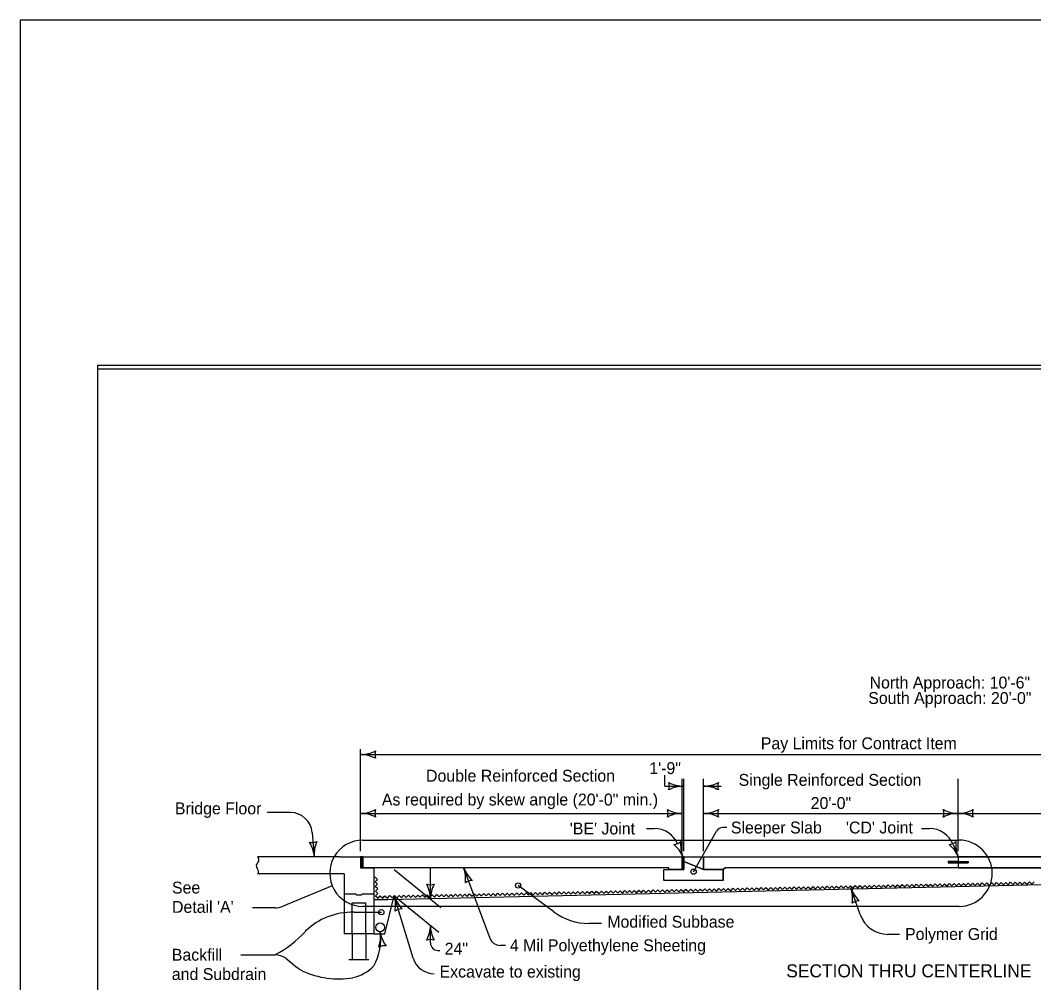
# Model space of a CAD drawing. Extents: x 10028 to 81668, y 6395 to 11634.
# Drawn here: x 20828 to 22193, y 9112 to 10409 of the extents above; entities that cross this region are included whole.
import ezdxf

# ---------------------------------------------------------------- set-up
doc = ezdxf.new("R2010")
doc.units = 0
for name, color, linetype in [('Default', 7, 'Continuous'), ('dsnCellElements', 7, 'Continuous'), ('dsnstdblockInterim', 7, 'Continuous'), ('dsnStdBlockNotModified', 7, 'Continuous'), ('dsnStdDimension', 7, 'Continuous'), ('dsnStgShadingPropPav', 7, 'Continuous'), ('ShtPlotIdentification', 7, 'Continuous')]:
    doc.layers.add(name, color=color, linetype=linetype)

msp = doc.modelspace()

# ---------------------------------------------------------------- linework, layer by layer
at = {"layer": 'Default'}
msp.add_lwpolyline([(20932.5, 9944), (24067.5, 9944), (24067.5, 7924), (20932.5, 7924)], close=True, dxfattribs=at)
at = {"layer": 'dsnCellElements'}
for p, q in [((21286.5, 9289.1), (21286.5, 9426.7)), ((21286.5, 9419.3), (22626, 9419.3)), ((21696.4, 9376.7), (21696.4, 9391.4)), ((21719.7, 9289.1), (21719.7, 9386.8)), ((21721.6, 9289.1), (21721.6, 9386.8)), ((21748.3, 9289.1), (21748.3, 9386.8)), ((22091.4, 9289.1), (22091.4, 9386.8)), ((21696.4, 9376.7), (21721.6, 9376.7)), ((21748.3, 9376.7), (21772.3, 9376.7)), ((21286.5, 9340.1), (21719.7, 9340.1)), ((21748.3, 9340.1), (22091.4, 9340.1)), ((22091.4, 9340.1), (22447.8, 9340.1)), ((21221.3, 9314.2), (21224.1, 9281.7)), ((21671.4, 9319.7), (21681.7, 9319.7)), ((21735, 9261.5), (21765.7, 9315.9)), ((21779.8, 9321), (21774.4, 9321)), ((22042.1, 9319.7), (22052.4, 9319.7)), ((21289.5, 9304), (22092.6, 9304)), ((21289.5, 9266.8), (21289.5, 9281.7)), ((21289.5, 9281.7), (21719.7, 9281.7)), ((21719.7, 9281.7), (21719.7, 9275.2)), ((21719.7, 9275.2), (21719.7, 9275.2)), ((21719.7, 9275.2), (21719.7, 9264.5)), ((21748.3, 9264.5), (21721.6, 9275.2)), ((21721.6, 9275.2), (21748.3, 9264.5)), ((21748.3, 9264.5), (21748.3, 9281.7)), ((21748.3, 9281.7), (22091.4, 9281.7)), ((22091.4, 9275.2), (22078, 9275.2)), ((22078, 9275.2), (22078, 9273.3)), ((22078, 9273.3), (22091.4, 9273.3)), ((22091.4, 9281.7), (22091.4, 9275.2)), ((22091.4, 9273.3), (22091.4, 9266.8)), ((21304.3, 9266.8), (21289.5, 9266.8)), ((21326.6, 9266.8), (21304.3, 9266.8)), ((21701.5, 9266.8), (21326.6, 9266.8)), ((21331.7, 9264.4), (21394.5, 9213.3)), ((21380.5, 9224.7), (21380.5, 9265.9)), ((21425.2, 9266.8), (21460.5, 9172.1)), ((21701.5, 9264.5), (21701.5, 9266.8)), ((21719.7, 9264.5), (21701.5, 9264.5)), ((21775, 9264.5), (21748.3, 9264.5)), ((21777.5, 9266.8), (21775, 9264.5)), ((21775, 9264.5), (21775, 9264.5)), ((22091.4, 9266.8), (21777.5, 9266.8)), ((21248.3, 9242.4), (21182.1, 9215.1)), ((21546.7, 9207.3), (21498.7, 9242.9)), ((21331.7, 9229.1), (21392, 9180)), ((21357.3, 9145.2), (21331.7, 9229.1)), ((21959.4, 9203.7), (21946.9, 9239.7)), ((21289.5, 9214.9), (22092.6, 9214.9)), ((21170.8, 9212.8), (21140.7, 9212.8)), ((21277.6, 9206.9), (21314.4, 9206.9)), ((21380.5, 9165.5), (21380.5, 9189.4)), ((21610.8, 9191.7), (21593.9, 9191.7)), ((22012.1, 9177.1), (21996.8, 9177.1)), ((21481.5, 9162.3), (21474.6, 9162.3)), ((21125.1, 9149.5), (21170.8, 9149.5)), ((21390.5, 9155.5), (21393, 9155.5))]:
    msp.add_line(p, q, dxfattribs=at)
for centre, radius, start, end in [((21681.8, 9285), 34.7, 22.5907, 90), ((21774.4, 9311), 10, 90, 150.5496), ((22052.4, 9285), 34.7, 22.5907, 90), ((21289.5, 9259.4), 44.6, 89.9996, 270), ((22092.6, 9259.4), 44.6, 270.0011, 90), ((21170.8, 9242.5), 29.7, 270, 292.4496), ((21275.4, 9116.1), 90.9, 88.6098, 134.2601), ((21593.9, 9270.9), 79.2, 233.4243, 270), ((21996.8, 9216.7), 39.6, 199.1769, 270), ((21107.3, 9274.8), 140.5, 296.876, 318.179), ((21242.3, 9169.9), 71.3, 330.5092, 8.5915), ((21474.6, 9177.3), 15, 200.4159, 270), ((21297.2, 9265), 163.6, 227.1442, 236.9942), ((21264.3, 9172.5), 55, 282.277, 316.7198), ((21385.7, 9153.8), 29.7, 196.9535, 270), ((21257.1, 9235.6), 118.5, 245.5915, 279.2221)]:
    msp.add_arc(centre, radius, start, end, dxfattribs=at)
at = {"layer": 'dsnstdblockInterim'}
msp.add_lwpolyline([(20932.5, 9939), (24067.5, 9939), (24067.5, 7929), (20932.5, 7929)], close=True, dxfattribs=at)
at = {"layer": 'dsnStdBlockNotModified'}
for centre, radius, start, end in [((21286.5, 9461.8), 42.5, 270, 298.0725), ((21286.5, 9376.8), 42.5, 61.9275, 90), ((21322.1, 9419.3), 16.4, 162.2666, 197.7334), ((21686, 9376.7), 16.4, 342.2666, 17.7333), ((21721.6, 9419.2), 42.5, 241.9275, 270), ((21748.3, 9419.2), 42.5, 270, 298.0725), ((21784, 9376.7), 16.4, 162.2666, 197.7334), ((21721.6, 9334.2), 42.5, 90, 118.0725), ((21748.3, 9334.2), 42.5, 61.9275, 90), ((21286.5, 9382.6), 42.5, 270, 298.0725), ((21286.5, 9297.6), 42.5, 61.9275, 90), ((21322.1, 9340.1), 16.4, 162.2666, 197.7334), ((21684.1, 9340.1), 16.4, 342.2666, 17.7333), ((21719.7, 9382.6), 42.5, 241.9275, 270), ((21719.7, 9297.6), 42.5, 90, 118.0725), ((21748.3, 9382.6), 42.5, 270, 298.0725), ((21748.3, 9297.6), 42.5, 61.9275, 90), ((21784, 9340.1), 16.4, 162.2666, 197.7334), ((22055.7, 9340.1), 16.4, 342.2666, 17.7333), ((22091.4, 9382.6), 42.5, 241.9275, 270), ((22091.4, 9297.6), 42.5, 90, 118.0725), ((22091.4, 9382.6), 42.5, 270, 298.0725), ((22091.4, 9297.6), 42.5, 61.9275, 90), ((22127, 9340.1), 16.4, 162.2666, 197.7334), ((21221.1, 9317.2), 16.4, 257.2333, 292.7), ((21181.8, 9278), 42.5, 4.9667, 33.0392), ((21266.5, 9285.4), 42.5, 156.8942, 184.9667), ((21707, 9314.6), 16.4, 274.8653, 310.332), ((21681.4, 9265.4), 42.5, 22.5986, 50.6711), ((21759.9, 9298), 42.5, 174.5261, 202.5986), ((22077.7, 9314.6), 16.4, 274.8653, 310.332), ((22052.1, 9265.4), 42.5, 22.5986, 50.6711), ((22130.6, 9298), 42.5, 174.5261, 202.5986), ((21465.1, 9281.6), 42.5, 200.3742, 228.4467), ((21385.4, 9252), 42.5, 352.3017, 20.3742), ((21437.7, 9233.4), 16.4, 92.6409, 128.1076), ((21372.4, 9241.5), 42.5, 196.9516, 225.0241), ((21291.1, 9216.7), 42.5, 348.8791, 16.9516), ((21987, 9253.6), 42.5, 199.1744, 227.2469), ((21906.7, 9225.7), 42.5, 351.1019, 19.1744), ((21958.6, 9206), 16.4, 91.4411, 126.9078), ((21342.1, 9195), 16.4, 89.2182, 124.6849), ((21338, 9189.4), 42.5, 331.9275, 360), ((21423, 9189.4), 42.5, 180, 208.0725), ((21270.8, 9174.2), 42.5, 340.519, 8.5915), ((21354.8, 9186.9), 42.5, 188.5915, 216.6639), ((21318.1, 9145.3), 16.4, 80.8581, 116.3248), ((21380.5, 9153.7), 16.4, 72.2666, 107.7334)]:
    msp.add_arc(centre, radius, start, end, dxfattribs=at)
at = {"layer": 'dsnStdDimension'}
msp.add_lwpolyline([(20828, 7824.5), (24172, 7824.5), (24172, 10408.5), (20828, 10408.5)], close=True, dxfattribs=at)
at = {"layer": 'dsnStgShadingPropPav'}
for centre in [(21735, 9261.5), (21498.7, 9242.9), (21314.4, 9206.9)]:
    msp.add_circle(centre, 3.54, dxfattribs=at)
at = {"layer": 'ShtPlotIdentification'}
for p, q in [((21192.2, 9341.3), (21160.5, 9341.3)), ((22084.4, 9298.3), (22091.4, 9281.7)), ((21258.3, 9281.7), (21147.7, 9281.7)), ((21258.3, 9281.7), (21286.5, 9281.7)), ((21286.5, 9281.7), (21286.5, 9266.7)), ((21289.5, 9281.7), (21286.5, 9281.7)), ((21286.5, 9280.4), (21287.4, 9281.3)), ((21286.5, 9278.3), (21289.5, 9281.3)), ((21289.5, 9281.3), (21286.5, 9281.3)), ((21286.5, 9276.2), (21289.5, 9279.2)), ((21286.5, 9274.1), (21289.5, 9277.1)), ((21286.5, 9272), (21289.5, 9275)), ((21286.5, 9269.9), (21289.5, 9272.9)), ((21286.5, 9267.8), (21289.5, 9270.8)), ((21289.5, 9281.7), (21289.5, 9266.7)), ((21289.5, 9281.7), (21719.7, 9281.7)), ((21719.7, 9264.5), (21719.7, 9281.7)), ((21721.6, 9281.7), (21719.7, 9281.7)), ((21719.7, 9281.7), (21721.6, 9281.7)), ((21719.7, 9264.5), (21719.7, 9281.7)), ((21721.6, 9281.7), (21748.3, 9281.7)), ((21721.6, 9281.7), (21721.6, 9264.5)), ((21721.6, 9281.7), (21721.6, 9264.5)), ((21721.6, 9281.7), (21748.3, 9281.7)), ((21721.6, 9264.5), (21721.6, 9281.7)), ((21748.3, 9264.5), (21748.3, 9281.7)), ((21748.3, 9281.7), (22444.4, 9281.7)), ((21748.3, 9281.7), (21748.3, 9264.5)), ((22078, 9275.2), (22104.7, 9275.2)), ((22078, 9275.2), (22078, 9273.3)), ((22078, 9273.3), (22104.7, 9273.3)), ((22444.4, 9281.7), (22091.4, 9281.7)), ((22091.4, 9281.7), (22091.4, 9275.2)), ((22091.4, 9281.7), (22091.4, 9266.8)), ((22091.4, 9275.2), (22104.7, 9275.2)), ((22104.7, 9273.3), (22091.4, 9273.3)), ((22091.4, 9273.3), (22091.4, 9266.8)), ((22104.7, 9275.2), (22104.7, 9273.3)), ((22104.7, 9275.2), (22104.7, 9273.3)), ((21264.2, 9258.8), (21147.7, 9258.8)), ((21264.2, 9258.8), (21264.2, 9178)), ((21286.5, 9266.7), (21304.3, 9266.7)), ((21287.5, 9266.7), (21289.5, 9268.7)), ((21701.5, 9266.8), (21289.5, 9266.8)), ((21326.6, 9266.8), (21303.3, 9266.8)), ((21304.3, 9266.8), (21304.3, 9178)), ((21694.9, 9249.6), (21694.9, 9264.5)), ((21694.9, 9264.5), (21701.5, 9264.5)), ((21694.9, 9249.6), (21694.9, 9264.5)), ((21694.9, 9264.5), (21701.5, 9264.5)), ((21701.5, 9264.5), (21701.5, 9266.8)), ((21701.5, 9264.5), (21721.6, 9264.5)), ((21701.5, 9264.5), (21721.6, 9264.5)), ((21721.6, 9264.5), (21719.7, 9264.5)), ((21775, 9264.5), (21748.3, 9264.5)), ((21748.3, 9264.5), (21775, 9264.5)), ((21775, 9264.5), (21777.5, 9266.8)), ((21775, 9249.6), (21775, 9264.5)), ((21775, 9264.5), (21775, 9249.6)), ((22430.7, 9266.8), (21777.5, 9266.8)), ((22091.4, 9266.8), (22430.7, 9266.8)), ((22440.3, 9249), (21323.1, 9223.8)), ((21775, 9249.6), (21694.9, 9249.6)), ((21775, 9249.6), (21694.9, 9249.6)), ((21264.2, 9231.7), (21279.3, 9231.7)), ((21281.2, 9229.9), (21279.3, 9231.7)), ((21287.3, 9229.9), (21281.2, 9229.9)), ((21287.3, 9229.9), (21289.2, 9231.7)), ((21289.2, 9231.7), (21304.3, 9231.7)), ((21319.2, 9178), (21331.7, 9229.1)), ((21275, 9178), (21275, 9219.6)), ((21275, 9219.6), (21293.5, 9219.6)), ((21293.5, 9178), (21293.5, 9219.6)), ((21323.1, 9223.8), (21304.3, 9223.8)), ((21304.3, 9178), (21264.2, 9178)), ((21275, 9178), (21275, 9143.1)), ((21293.5, 9178), (21293.5, 9143.1)), ((21304.3, 9178), (21319.2, 9178)), ((21270.7, 9143.1), (21297.7, 9143.1))]:
    msp.add_line(p, q, dxfattribs=at)
for points in [[(22091.4, 9281.7), (22091.4, 9281.7)], [(21308.3, 9227.3), (21306.5, 9229), (21309.6, 9232.2), (21306.4, 9235.3), (21309.5, 9238.6), (21306.2, 9241.7), (21309.3, 9244.9), (21306.1, 9248), (21309.2, 9251.2), (21305.9, 9254.3), (21306.1, 9254.5)], [(21897.4, 9239.9), (21899, 9238.4), (21902.1, 9241.6), (21905.3, 9238.5), (21908.4, 9241.7), (21911.7, 9238.6), (21914.8, 9241.9), (21918, 9238.8), (21921.1, 9242), (21924.3, 9238.9), (21927.4, 9242.2), (21930.7, 9239.1), (21933.8, 9242.3), (21937, 9239.2), (21940.1, 9242.4), (21943.3, 9239.3), (21946.4, 9242.6), (21949.7, 9239.5), (21952.8, 9242.7), (21956, 9239.6), (21959.1, 9242.8), (21962.3, 9239.7), (21965.4, 9243), (21968.7, 9239.9), (21971.8, 9243.1), (21973.4, 9241.6)], [(21973.4, 9241.6), (21975, 9240), (21978.1, 9243.2), (21981.3, 9240.1), (21984.4, 9243.4), (21987.7, 9240.3), (21990.8, 9243.5), (21994, 9240.4), (21997.1, 9243.6), (22000.3, 9240.5), (22003.5, 9243.8), (22006.7, 9240.7), (22009.8, 9243.9), (22013, 9240.8), (22016.1, 9244.1), (22019.4, 9241), (22022.5, 9244.2), (22025.7, 9241.1), (22028.8, 9244.3), (22032, 9241.2), (22035.1, 9244.5), (22038.4, 9241.4), (22041.5, 9244.6), (22044.7, 9241.5), (22047.8, 9244.7), (22049.4, 9243.2)], [(22049.4, 9243.2), (22051, 9241.6), (22054.1, 9244.9), (22057.4, 9241.8), (22060.5, 9245), (22063.7, 9241.9), (22066.8, 9245.1), (22070, 9242), (22073.1, 9245.3), (22076.4, 9242.2), (22079.5, 9245.4), (22082.7, 9242.3), (22085.8, 9245.5), (22089, 9242.4), (22092.1, 9245.7), (22095.4, 9242.6), (22098.5, 9245.8), (22101.7, 9242.7), (22104.8, 9246), (22108, 9242.9), (22111.1, 9246.1), (22114.4, 9243), (22117.5, 9246.2), (22120.7, 9243.1), (22123.8, 9246.4), (22125.4, 9244.8)], [(22125.4, 9244.8), (22127, 9243.3), (22130.1, 9246.5), (22133.4, 9243.4), (22136.5, 9246.6), (22139.7, 9243.5), (22142.8, 9246.8), (22146, 9243.7), (22149.1, 9246.9), (22152.4, 9243.8), (22155.5, 9247), (22158.7, 9243.9), (22161.8, 9247.2), (22165, 9244.1), (22168.1, 9247.3), (22171.4, 9244.2), (22174.5, 9247.4), (22177.7, 9244.3), (22180.8, 9247.6), (22184.1, 9244.5), (22187.2, 9247.7), (22190.4, 9244.6), (22193.5, 9247.8)], [(21306.6, 9228.9), (21306.6, 9228.9), (21309.9, 9225.8), (21313, 9229), (21316.2, 9225.9), (21319.3, 9229.1), (21322.6, 9226), (21325.7, 9229.3), (21328.9, 9226.2), (21332, 9229.4), (21335.2, 9226.3), (21338.3, 9229.6), (21341.6, 9226.5), (21344.7, 9229.7), (21347.9, 9226.6), (21351, 9229.8), (21354.2, 9226.7), (21357.3, 9230), (21360.6, 9226.9), (21363.7, 9230.1), (21365.3, 9228.5)], [(21365.3, 9228.5), (21366.9, 9227), (21370, 9230.2), (21373.2, 9227.1), (21376.3, 9230.4), (21379.6, 9227.3), (21382.7, 9230.5), (21385.9, 9227.4), (21389, 9230.6), (21392.2, 9227.5), (21395.3, 9230.8), (21398.6, 9227.7), (21401.7, 9230.9), (21404.9, 9227.8), (21408, 9231), (21411.2, 9227.9), (21414.3, 9231.2), (21417.6, 9228.1), (21420.7, 9231.3), (21423.9, 9228.2), (21427, 9231.4), (21430.2, 9228.3), (21433.3, 9231.6), (21436.6, 9228.5), (21439.7, 9231.7), (21441.3, 9230.2)], [(21441.3, 9230.2), (21442.9, 9228.6), (21446, 9231.9), (21449.2, 9228.8), (21452.3, 9232), (21455.6, 9228.9), (21458.7, 9232.1), (21461.9, 9229), (21465, 9232.3), (21468.2, 9229.2), (21471.3, 9232.4), (21474.6, 9229.3), (21477.7, 9232.5), (21480.9, 9229.4), (21484, 9232.7), (21487.2, 9229.6), (21490.3, 9232.8), (21493.6, 9229.7), (21496.7, 9232.9), (21499.9, 9229.8), (21503, 9233.1), (21506.3, 9230), (21509.4, 9233.2), (21512.6, 9230.1), (21515.7, 9233.4), (21517.3, 9231.8)], [(21517.3, 9231.8), (21518.9, 9230.2), (21522, 9233.5), (21525.3, 9230.4), (21528.4, 9233.6), (21531.6, 9230.5), (21534.7, 9233.8), (21537.9, 9230.7), (21541, 9233.9), (21544.3, 9230.8), (21547.4, 9234), (21550.6, 9230.9), (21553.7, 9234.2), (21556.9, 9231.1), (21560, 9234.3), (21563.3, 9231.2), (21566.4, 9234.4), (21569.6, 9231.3), (21572.7, 9234.6), (21575.9, 9231.5), (21579, 9234.7), (21582.3, 9231.6), (21585.4, 9234.8), (21588.6, 9231.7), (21591.7, 9235), (21593.3, 9233.4)], [(21593.3, 9233.4), (21594.9, 9231.9), (21598, 9235.1), (21601.3, 9232), (21604.4, 9235.2), (21607.6, 9232.1), (21610.7, 9235.4), (21613.9, 9232.3), (21617, 9235.5), (21620.3, 9232.4), (21623.4, 9235.7), (21626.6, 9232.6), (21629.7, 9235.8), (21632.9, 9232.7), (21636, 9235.9), (21639.3, 9232.8), (21642.4, 9236.1), (21645.6, 9233), (21648.7, 9236.2), (21651.9, 9233.1), (21655.1, 9236.3), (21658.3, 9233.2), (21661.4, 9236.5), (21664.6, 9233.4), (21667.7, 9236.6), (21669.3, 9235)], [(21669.3, 9235), (21671, 9233.5), (21674.1, 9236.7), (21677.3, 9233.6), (21680.4, 9236.9), (21683.6, 9233.8), (21686.7, 9237), (21690, 9233.9), (21693.1, 9237.1), (21696.3, 9234), (21699.4, 9237.3), (21702.6, 9234.2), (21705.7, 9237.4), (21709, 9234.3), (21712.1, 9237.5), (21715.3, 9234.4), (21718.4, 9237.7), (21721.6, 9234.6), (21724.7, 9237.8), (21728, 9234.7), (21731.1, 9238), (21734.3, 9234.9), (21737.4, 9238.1), (21740.6, 9235), (21743.7, 9238.2), (21745.4, 9236.7)], [(21745.4, 9236.7), (21747, 9235.1), (21750.1, 9238.4), (21753.3, 9235.3), (21756.4, 9238.5), (21759.6, 9235.4), (21762.7, 9238.6), (21766, 9235.5), (21769.1, 9238.8), (21772.3, 9235.7), (21775.4, 9238.9), (21778.6, 9235.8), (21781.7, 9239), (21785, 9235.9), (21788.1, 9239.2), (21791.3, 9236.1), (21794.4, 9239.3), (21797.6, 9236.2), (21800.7, 9239.4), (21804, 9236.3), (21807.1, 9239.6), (21810.3, 9236.5), (21813.4, 9239.7), (21816.6, 9236.6), (21819.7, 9239.9), (21821.4, 9238.3)], [(21821.4, 9238.3), (21823, 9236.8), (21826.1, 9240), (21829.3, 9236.9), (21832.4, 9240.1), (21835.7, 9237), (21838.8, 9240.3), (21842, 9237.2), (21845.1, 9240.4), (21848.3, 9237.3), (21851.4, 9240.5), (21854.7, 9237.4), (21857.8, 9240.7), (21861, 9237.6), (21864.1, 9240.8), (21867.3, 9237.7), (21870.4, 9240.9), (21873.7, 9237.8), (21876.8, 9241.1), (21880, 9238), (21883.1, 9241.2), (21886.3, 9238.1), (21889.4, 9241.3), (21892.7, 9238.2), (21895.8, 9241.5), (21897.4, 9239.9)]]:
    msp.add_lwpolyline(points, dxfattribs=at)
msp.add_circle((21312.8, 9186.5), 5.94, dxfattribs=at)
for centre, radius, start, end in [((21191.7, 9311.6), 29.7, 4.9696, 89.1065), ((21380.5, 9260.5), 16.5, 252.2666, 287.7333), ((21337.8, 9224.7), 42.7, 360, 28.0725), ((21423.3, 9224.7), 42.7, 151.9275, 180), ((21390.5, 9165.5), 10, 180, 270), ((21170.8, 9121.8), 27.7, 56.8248, 90)]:
    msp.add_arc(centre, radius, start, end, dxfattribs=at)
msp.add_spline([(21147.7, 9281.7), (21148.8, 9275.7), (21145.8, 9269.7), (21148.6, 9262.1), (21148.2, 9258.8)], degree=3, dxfattribs=at)

# ---------------------------------------------------------------- texts
at = {"layer": 'dsnCellElements'}
for s, p in [('North Approach: 10\'-6"', (21972, 9508.3)), ('South Approach: 20\'-0"', (21970.2, 9487.5)), ('Pay Limits for Contract Item', (21825.5, 9426.5)), ('1\'-9"', (21675.3, 9393)), ('Double Reinforced Section', (21374.6, 9382.8)), ('Single Reinforced Section', (21795.6, 9377.2)), ('As required by skew angle (20\'-0" min.)', (21315.1, 9350.7)), ('Bridge Floor', (21036.3, 9338.8)), ('20\'-0"', (21892.7, 9346)), ("'BE' Joint", (21568.2, 9311.7)), ('Sleeper Slab', (21785.2, 9313)), ("'CD' Joint", (21940.2, 9313)), ('See', (21032.4, 9232.1)), ("Detail 'A'", (21032.4, 9206.1)), ('Modified Subbase', (21618.7, 9186.1)), ('Polymer Grid', (22019.8, 9169.5)), ('24"', (21399.7, 9149.8)), ('4 Mil Polyethylene Sheeting', (21487.6, 9154.3)), ('Backfill', (21032.2, 9141.6)), ('and Subdrain', (21032.2, 9115.6)), ('Excavate to existing', (21392.8, 9118.9))]:
    msp.add_text(s, height=16, dxfattribs=at).set_placement(p)
at = {"layer": 'ShtPlotIdentification'}
msp.add_text('SECTION THRU CENTERLINE', height=17.5, dxfattribs=at).set_placement((21859.8, 9119.2))

doc.saveas('drawing.dxf')
